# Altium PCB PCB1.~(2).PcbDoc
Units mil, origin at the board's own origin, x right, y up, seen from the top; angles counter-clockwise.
Board outline 6000 x 4000 mil, 2 copper layers (Top Layer, Bottom Layer); 7 components, 7 nets, 21 pads, 0 vias.
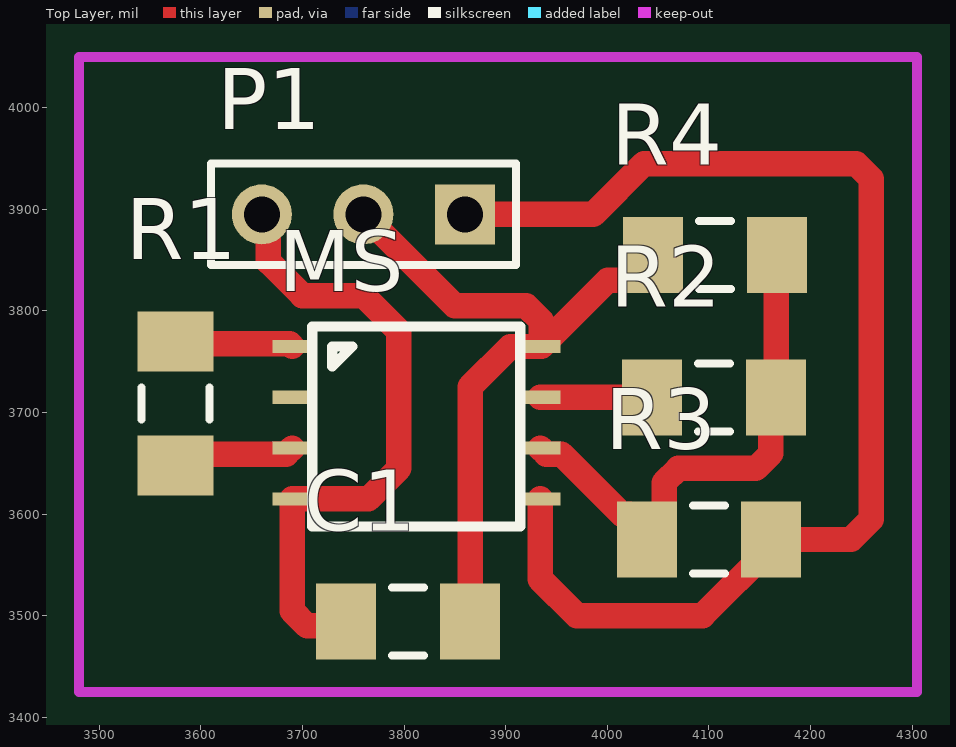
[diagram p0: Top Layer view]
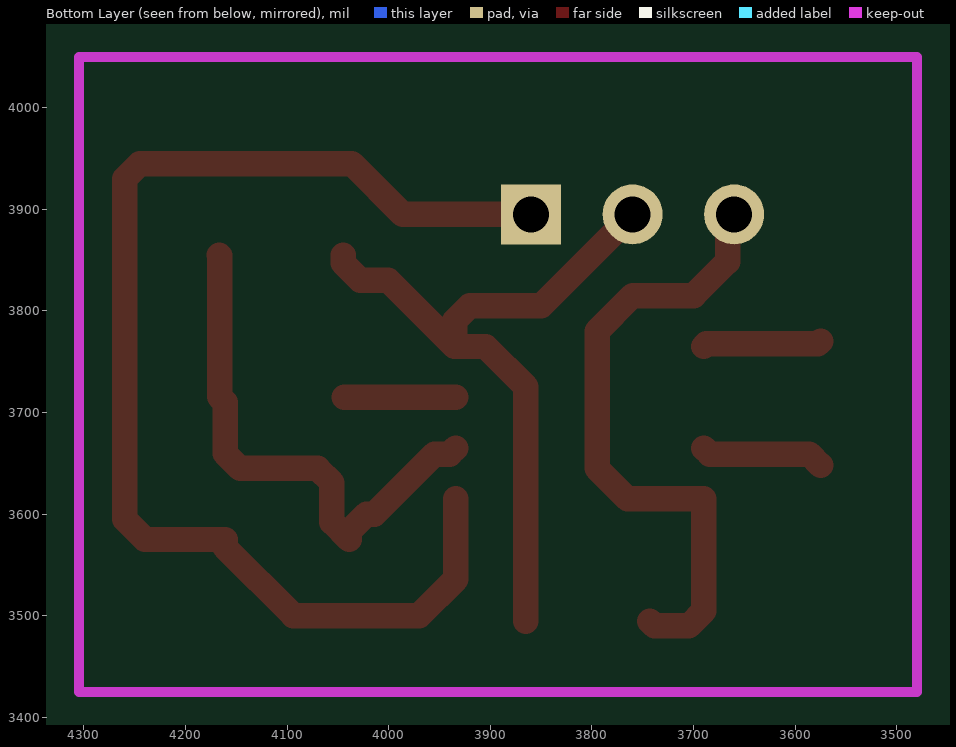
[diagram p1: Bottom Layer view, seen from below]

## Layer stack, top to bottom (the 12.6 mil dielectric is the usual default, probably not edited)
Top Solder: solder mask 0.4, Solder Resist, Dk 3.5
Top Layer: signal copper 1.4
Dielectric 1: dielectric 12.6, FR-4, Dk 4.8
Bottom Layer: signal copper 1.4
Bottom Solder: solder mask 0.4, Solder Resist, Dk 3.5

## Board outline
1000,1000 7000,1000 7000,5000 1000,5000

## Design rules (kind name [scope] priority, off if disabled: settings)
Clearance [All] p1: gap=10 ignorepadtopadclearanceinfootprint=FALSE except(0: Arc-Hole Track-Hole SMDPad-Hole THPad-Hole Via-Hole Fill-Hole Poly-Hole Region-Hole Text-Hole)
PolygonConnect [All] p1: connectstyle=Relief reliefconductorwidth=10 reliefentries=4 polygonreliefangle="90 Angle" airgapwidth=10
RoutingVias [All] p1: holewidth=28 width=50 viastyle="Through Hole" minholewidth=28 minwidth=50 maxholewidth=28 maxwidth=50
SolderMaskExpansion [All] p1: expansion=4
Width [All] p1: maxlimit=26 minlimit=25 preferedwidth=25 minimp=50.000000 maximp=50.000000 favimp=50.000000
30 further rules are at their usual default settings.

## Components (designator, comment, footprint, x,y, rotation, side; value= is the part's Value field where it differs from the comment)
C1 "Cap" CAPC3216M 3803.98,3494.53 r0 top value=0.1muF
MS "MagnetSensor" AD22151 3690,3765 r0 top
P1 "Header 3" HDR1X3 3860,3895 r180 top (schematic designator P?)
R1 "Res3" RESC3216M 3575,3708.98 r90 top value=4.7K
R2 "Res3" RESC3216M 4105,3715 r0 top value=4.7K
R3 "Res3" RESC3216M 4100,3575 r0 top value=4.7K
R4 "Res3" RESC3216M 4106.02,3855 r0 top value=4.7K

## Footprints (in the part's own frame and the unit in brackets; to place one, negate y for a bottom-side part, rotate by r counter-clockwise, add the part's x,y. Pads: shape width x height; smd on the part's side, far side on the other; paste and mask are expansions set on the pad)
AD22151 [mm] "Magnetic Sensor"
  rect 1x0.33 smd: 1(0,0) 2(0,-1.27) 3(0,-2.54) 4(0,-3.81) 5(6.2,-3.81) 6(6.2,-2.54) 7(6.2,-1.27) 8(6.2,0)
  silkscreen extent 0.5,-4.5 5.7,0.5
CAPC3216M [mm] "Chip Capacitor, Body 3.2x1.6mm, IPC Low Density"
  rect 1.5x1.9 smd: 1(-1.55,0) 2(1.55,0)
  silkscreen extent -0.4,-0.85 0.4,0.85, body extent -1.7,-0.9 1.7,0.9, height 1.35
HDR1X3 [mm] "Connector; Header; 3 Position"
  rect 1.5x1.5 hole 0.9: 1(0,0)
  round 1.5 hole 0.9: 2(2.54,0) 3(5.08,0)
  silkscreen extent -1.27,-1.27 6.35,1.27
RESC3216M [mm] "Chip Resistor, Body 3.2x1.6mm, IPC Low Density"
  rect 1.5x1.9 smd: 1(-1.55,0) 2(1.55,0)
  silkscreen extent -0.4,-0.85 0.4,0.85, body extent -1.68,-0.87 1.68,0.87, height 0.71

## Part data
C1: "Capacitor"
MS: library part Component_1
P1: "Header, 3-Pin"
R1 R2 R3 R4: "Resistor"

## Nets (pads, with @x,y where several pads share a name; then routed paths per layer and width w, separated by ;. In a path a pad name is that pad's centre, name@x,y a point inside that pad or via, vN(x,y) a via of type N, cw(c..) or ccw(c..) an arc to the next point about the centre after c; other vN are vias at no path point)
NetC1_1: C1.1 MS.4 P1.3 | length 629.7
  Top Layer w25: P1.3 3666.52,3888.48 3666.52,3848.48 3700,3815 3760,3815 3795,3780 3795,3645 3765,3615 MS.4 3690,3504.64 3704.64,3490 3738.43,3490 C1.1
NetC1_2: C1.2 MS.8 P1.2 R4.1 | length 714.5
  Top Layer w10: C1.2 C1.2@3865.91,3495.43
  Top Layer w25: P1.2 3850,3805 3920.36,3805 3935,3790.36 3935,3765.91 MS.8 ; C1.2 3865,3725.36 3904.64,3765 MS.8 ; R4.1 4045,3847.13 4027.97,3830.1 4000.37,3830.1 3935.28,3765 MS.8
NetMS_1: MS.1 R1.2 | length 117.1
  Top Layer w25: R1.2 3577.5,3767.5 3687.5,3767.5 MS.1
NetMS_3: MS.3 R1.1 | length 122.1
  Top Layer w25: R1.1 3586.04,3659 3684,3659 MS.3
NetMS_5: MS.5 P1.1 R3.2 | length 1225.8
  Top Layer w25: P1.1 3986.25,3895 4036.25,3945 4245,3945 4260,3930 4260,3595 4240,3575 R3.2 4161.02,3567.13 4093.9,3500 3970,3500 3934.09,3535.91 MS.5
NetMS_6: MS.6 R2.2 R3.1 R4.2 | length 524.6
  Top Layer w25: MS.6 3940.1,3659 3954.98,3659 4014.07,3599.9 4021.95,3599.9 4038.98,3582.87 R3.1 4056,3592.03 4056,3631 4070,3645 4146.38,3645 4161.02,3659.64 4161.02,3710 R2.2 4166.54,3715.51 4166.54,3854.49 R4.2
NetMS_7: MS.7 R2.1 | length 109.9
  Top Layer w25: MS.7 R2.1
pads on no net: MS.2

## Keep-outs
Keep-Out Layer:
  lines w10: 3485,4050 3480,4050 ; 3480,4050 4305,4050 4305,3425 3480,3425 3480,4050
